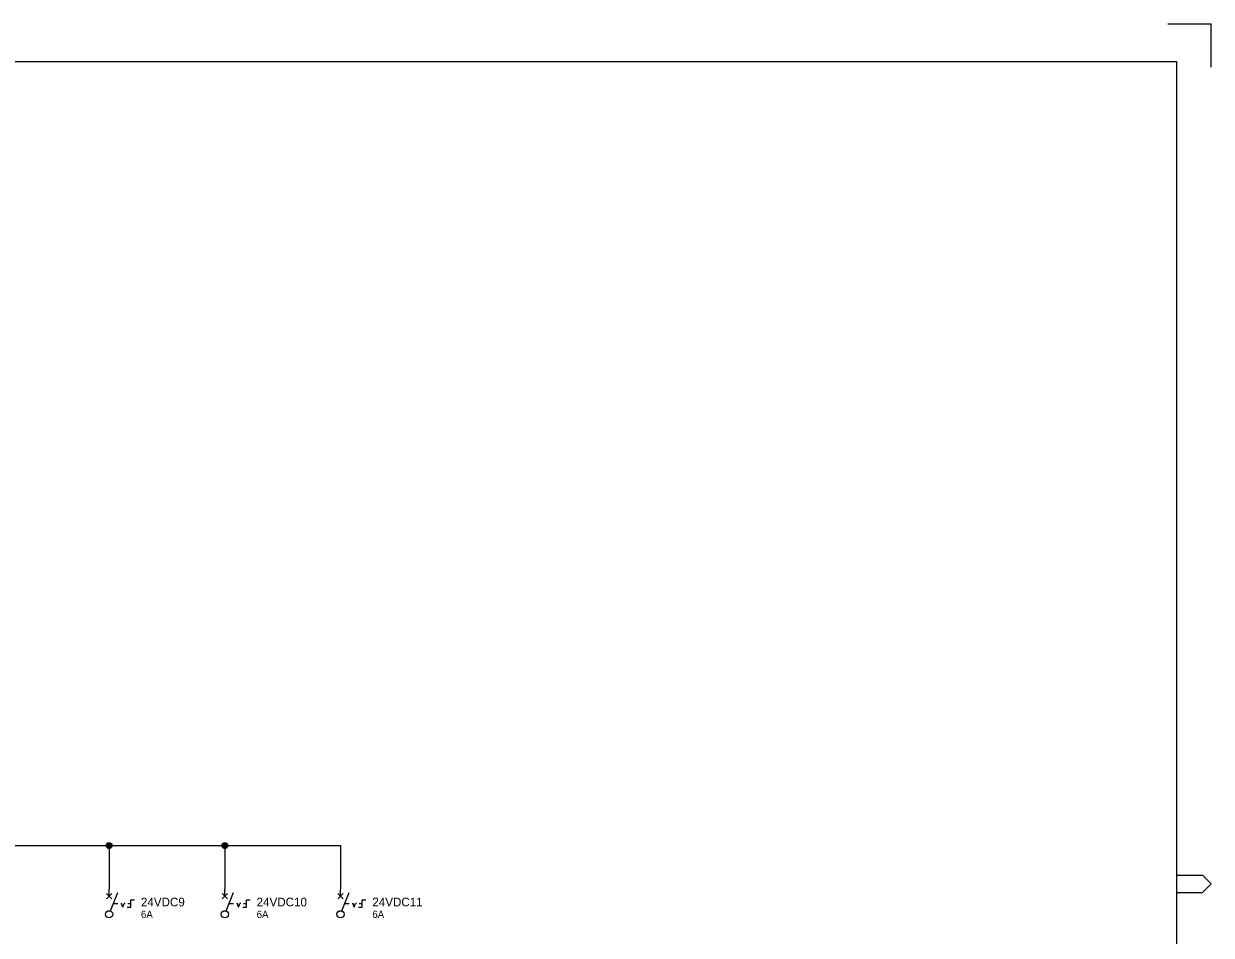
# Model space of a CAD drawing. Extents: x 0 to 841, y 0 to 594.
# Drawn here: x 430.5 to 841, y 279 to 594 of the extents above; entities that cross this region are included whole.
import ezdxf

# ---------------------------------------------------------------- set-up
doc = ezdxf.new("R2010")
doc.units = 0
for name, color, linetype in [('A1BORDER', 7, 'Continuous'), ('Level 1', 7, 'Continuous'), ('Level 10', 7, 'Continuous')]:
    doc.layers.add(name, color=color, linetype=linetype)

msp = doc.modelspace()

# ---------------------------------------------------------------- linework, layer by layer
at = {"layer": 'A1BORDER'}
for p, q in [((826, 594), (841, 594)), ((841, 579), (841, 594)), ((28, 581), (829, 581)), ((829, 581), (829, 15)), ((829, 299.76), (838, 299.76)), ((838, 299.76), (841, 296.76)), ((838, 293.76), (841, 296.76)), ((829, 293.76), (838, 293.76))]:
    msp.add_line(p, q, dxfattribs=at)
at = {"layer": 'Level 1'}
for p, q in [((80, 310), (540, 310)), ((460, 310), (460, 295)), ((500, 310), (500, 295)), ((540, 310), (540, 295)), ((459.06, 293.44), (460.94, 291.56)), ((460.94, 293.44), (459.06, 291.56)), ((460, 292.5), (460, 295)), ((460.46, 287.41), (463, 293.75)), ((499.06, 293.44), (500.94, 291.56)), ((500.94, 293.44), (499.06, 291.56)), ((500, 292.5), (500, 295)), ((500.46, 287.41), (503, 293.75)), ((539.06, 293.44), (540.94, 291.56)), ((540.94, 293.44), (539.06, 291.56)), ((540, 292.5), (540, 295)), ((540.46, 287.41), (543, 293.75))]:
    msp.add_line(p, q, dxfattribs=at)
for centre in [(460, 286.25), (500, 286.25), (540, 286.25)]:
    msp.add_circle(centre, 1.25, dxfattribs=at)
at = {"layer": 'Level 10'}
for p, q in [((459, 310), (460.99, 310)), ((459.05, 310.3), (460.95, 310.3)), ((459.05, 309.7), (460.95, 309.7)), ((459.2, 310.6), (460.8, 310.6)), ((459.2, 309.4), (460.8, 309.4)), ((459.56, 310.9), (460.44, 310.9)), ((459.56, 309.1), (460.44, 309.1)), ((460, 311), (460, 311)), ((499, 310), (500.99, 310)), ((499.05, 310.3), (500.95, 310.3)), ((499.05, 309.7), (500.95, 309.7)), ((499.2, 310.6), (500.8, 310.6)), ((499.2, 309.4), (500.8, 309.4)), ((499.56, 310.9), (500.44, 310.9)), ((499.56, 309.1), (500.44, 309.1)), ((500, 311), (500, 311)), ((461.5, 290), (463, 290)), ((464, 290), (464.33, 290)), ((464.75, 288.75), (464.33, 290)), ((464.75, 288.75), (465.17, 290)), ((465.5, 290), (465.17, 290)), ((466.25, 288.75), (467.5, 288.75)), ((466.5, 290), (467.5, 290)), ((467.5, 288.75), (467.5, 291.25)), ((467.5, 291.25), (468.75, 291.25)), ((501.5, 290), (503, 290)), ((504, 290), (504.33, 290)), ((504.75, 288.75), (504.33, 290)), ((504.75, 288.75), (505.17, 290)), ((505.5, 290), (505.17, 290)), ((506.25, 288.75), (507.5, 288.75)), ((506.5, 290), (507.5, 290)), ((507.5, 288.75), (507.5, 291.25)), ((507.5, 291.25), (508.75, 291.25)), ((541.5, 290), (543, 290)), ((544, 290), (544.33, 290)), ((544.75, 288.75), (544.33, 290)), ((544.75, 288.75), (545.17, 290)), ((545.5, 290), (545.17, 290)), ((546.25, 288.75), (547.5, 288.75)), ((546.5, 290), (547.5, 290)), ((547.5, 288.75), (547.5, 291.25)), ((547.5, 291.25), (548.75, 291.25))]:
    msp.add_line(p, q, dxfattribs=at)
for centre in [(460, 310), (500, 310)]:
    msp.add_circle(centre, 1, dxfattribs=at)

# ---------------------------------------------------------------- texts
at = {"layer": 'Level 1'}
for s, height, p in [('24VDC9', 3, (471, 289)), ('24VDC10', 3, (511, 289)), ('24VDC11', 3, (551, 289)), ('6A', 2.5, (471, 285)), ('6A', 2.5, (511, 285)), ('6A', 2.5, (551, 285))]:
    msp.add_text(s, height=height, dxfattribs=at).set_placement(p)

doc.saveas('drawing.dxf')
